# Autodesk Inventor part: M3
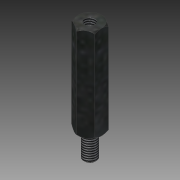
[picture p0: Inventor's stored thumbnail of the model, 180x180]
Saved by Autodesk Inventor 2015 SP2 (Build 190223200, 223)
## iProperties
Created: 2012-08
Part Number: M3
Material: Stahl
Document SubType Name: Modeling
Designer: rYan
Density: 7.85 g/cm^3
Mass: 1.74537 g
Surface Area: 3.04272 cm^2
Volume: 0.22234 cm^3
Appearance: Platte
Author: rYan
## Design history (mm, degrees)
derived "Abstandsbolzen Typ B.ipt"
feature "Volumenkörper1::Abstandsbolzen Typ B.ipt"
tag "Bezeichnung1"
node "Volumenkörper1"
other parameters: "SW" = 5.5, "L" = 22, "d2" = 0, "l_" = 7, "d9" = 118 deg, "GA_" = 3, "A_" = 6, "d13" = 0, "d17" = 0.25, "d20" = 45 deg
